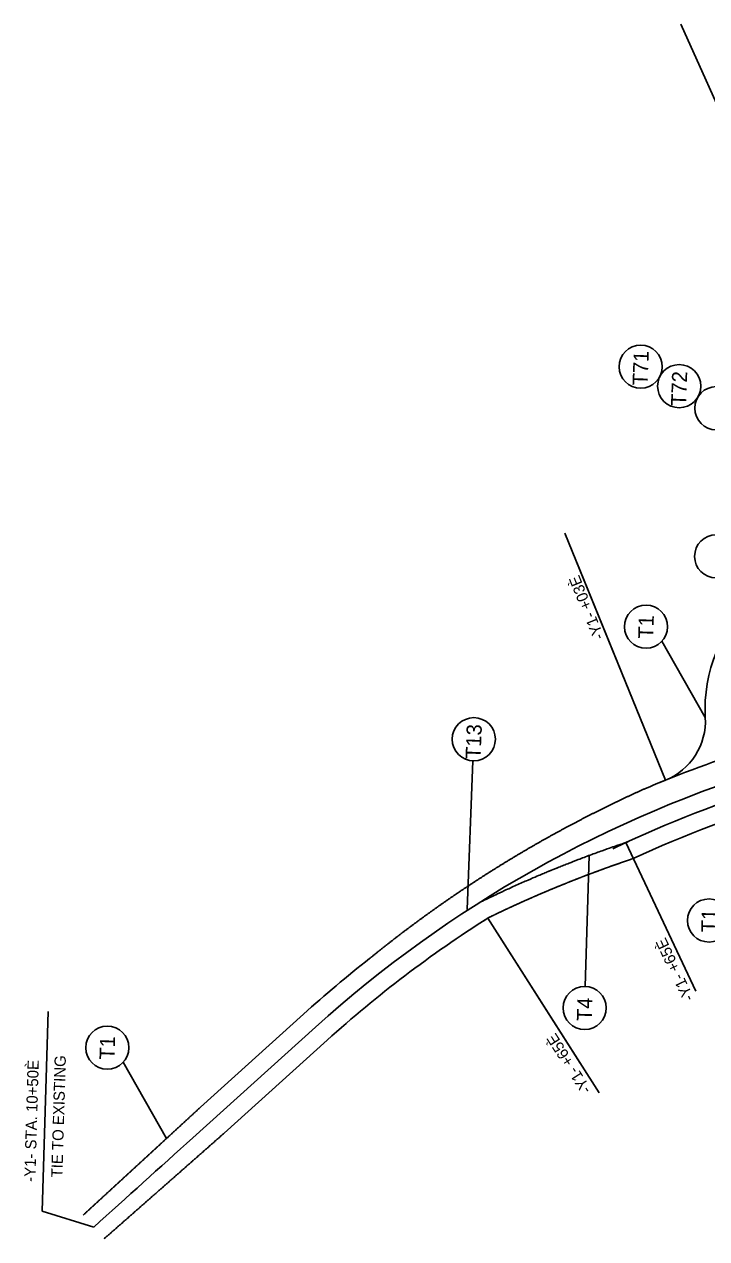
# Model space of a CAD drawing. Extents: x 1657109 to 2100937, y 684916 to 883211.
# Drawn here: x 2097100 to 2097527, y 685545 to 686305 of the extents above; entities that cross this region are included whole.
import ezdxf

# ---------------------------------------------------------------- set-up
doc = ezdxf.new("R2010")
doc.units = 0
for name, color, linetype in [('Prop CMT Pvmt Gravel', 7, 'Continuous'), ('Prop Conc 1ft 6in Curb and Gutter', 7, 'Continuous'), ('Prop Conc 2ft 6in Curb and Gutter', 7, 'Continuous'), ('Prop Dimension', 7, 'Continuous'), ('Prop Guardrail Anchor Unit CELL', 7, 'Continuous'), ('Prop Lane Arrow CELL', 7, 'Continuous'), ('Prop Sign E Chevron Right', 7, 'Continuous'), ('Scratch_Level_1', 7, 'Continuous')]:
    doc.layers.add(name, color=color, linetype=linetype)

msp = doc.modelspace()

# ---------------------------------------------------------------- linework, layer by layer
at = {"layer": 'Prop CMT Pvmt Gravel'}
for p, q in [((2097501.27, 685832.17), (2097438.41, 685986.71)), ((2097526.23, 685871.46), (2097499.11, 685919.12)), ((2097377.27, 685751.33), (2097380.84, 685844.33)), ((2097476.52, 685793.11), (2097520.28, 685700.17)), ((2097453.53, 685785.07), (2097451.14, 685703.18)), ((2097390.08, 685745.9), (2097459.86, 685636.58)), ((2097114.97, 685687.51), (2097111.34, 685562.51)), ((2097189.15, 685608.07), (2097162.04, 685655.73)), ((2097143.56, 685552.56), (2097111.34, 685562.51))]:
    msp.add_line(p, q, dxfattribs=at)
for centre in [(2097485.79, 686090.88), (2097509.88, 686078.71), (2097533.07, 686064.92), (2097533.02, 685972.21), (2097489.13, 685928.21), (2097381.36, 685857.82), (2097528.55, 685744.4), (2097450.75, 685689.68), (2097152.05, 685664.82)]:
    msp.add_circle(centre, 13.5, dxfattribs=at)
at = {"layer": 'Prop Conc 1ft 6in Curb and Gutter'}
msp.add_arc((2097791.55, 685113.58), 749, 106.65716, 114.87261, dxfattribs=at)
at = {"layer": 'Prop Conc 2ft 6in Curb and Gutter'}
msp.add_lwpolyline([(2097430.99, 685776.28), (2097431, 685776.28), (2097431, 685776.29)], dxfattribs=at)
for points in [[(2097431, 685776.29), (2097431.12, 685776.33), (2097431.3, 685776.41), (2097431.48, 685776.48), (2097431.6, 685776.53), (2097431.67, 685776.56), (2097431.84, 685776.63), (2097431.96, 685776.68), (2097432.11, 685776.74), (2097432.16, 685776.76), (2097432.2, 685776.77), (2097432.23, 685776.79), (2097432.25, 685776.79), (2097432.32, 685776.82), (2097432.86, 685777.04), (2097434.36, 685777.65), (2097437.73, 685779), (2097440.63, 685780.14), (2097446.42, 685782.4), (2097454.18, 685785.35), (2097461.98, 685788.16), (2097467.85, 685790.23), (2097470.79, 685791.25), (2097473.86, 685792.29), (2097474.97, 685792.66), (2097475.15, 685792.72), (2097475.21, 685792.74), (2097475.33, 685792.78), (2097475.46, 685792.83), (2097475.61, 685792.88), (2097475.7, 685792.91), (2097475.76, 685792.93), (2097475.79, 685792.94), (2097475.94, 685792.99), (2097476.07, 685793.03), (2097476.26, 685793.1), (2097476.32, 685793.12), (2097476.39, 685793.14), (2097476.4, 685793.14), (2097476.4, 685793.14), (2097476.41, 685793.14), (2097476.41, 685793.15), (2097476.41, 685793.15), (2097476.42, 685793.15), (2097476.44, 685793.16), (2097476.49, 685793.17), (2097476.66, 685793.23), (2097477.05, 685793.36), (2097477.42, 685793.48), (2097477.66, 685793.56)], [(2097385.26, 685755.79), (2097385.38, 685755.85), (2097385.55, 685755.93), (2097385.73, 685756.02), (2097385.85, 685756.07), (2097385.91, 685756.1), (2097386.08, 685756.19), (2097386.2, 685756.25), (2097386.34, 685756.32), (2097386.39, 685756.34), (2097386.43, 685756.36), (2097386.46, 685756.37), (2097386.47, 685756.38), (2097386.55, 685756.42), (2097387.08, 685756.67), (2097388.54, 685757.38), (2097391.84, 685758.97), (2097394.67, 685760.31), (2097400.35, 685762.97), (2097407.94, 685766.45), (2097415.6, 685769.8), (2097421.36, 685772.27), (2097424.24, 685773.49), (2097427.62, 685774.89), (2097429.13, 685775.52), (2097429.67, 685775.74), (2097429.74, 685775.77), (2097429.75, 685775.77), (2097429.76, 685775.78), (2097429.79, 685775.79), (2097429.84, 685775.81), (2097429.88, 685775.83), (2097430.04, 685775.89), (2097430.16, 685775.94), (2097430.34, 685776.01), (2097430.4, 685776.04), (2097430.52, 685776.09), (2097430.69, 685776.16), (2097430.87, 685776.23), (2097430.99, 685776.28)]]:
    msp.add_open_spline(points, degree=3, dxfattribs=at)
at = {"layer": 'Prop Dimension'}
for points in [[(2097497.79, 685830.75), (2097501.27, 685832.17), (2097445.89, 685968.3)], [(2097468.46, 685789.32), (2097476.52, 685793.11), (2097520.28, 685700.17)], [(2097387.18, 685744.05), (2097390.09, 685745.9), (2097447.99, 685655.16)]]:
    msp.add_lwpolyline(points, dxfattribs=at)
at = {"layer": 'Prop Guardrail Anchor Unit CELL'}
for p, q in [((2097210.46, 685627.69), (2097274.89, 685685.86)), ((2097225.2, 685611.36), (2097289.63, 685669.53))]:
    msp.add_line(p, q, dxfattribs=at)
for centre, radius, start, end in [((2097621.08, 685876.69), 95, 132.43424, 183.15611), ((2097486.29, 685869.26), 40, 291.99663, 3.15611), ((2097791.55, 685113.58), 775, 111.99663, 112.98788), ((2097791.55, 685113.58), 738, 106.65716, 114.87261), ((2097791.55, 685113.58), 749, 122.41153, 132.07604), ((2097791.55, 685113.58), 771, 128.06571, 132.07604)]:
    msp.add_arc(centre, radius, start, end, dxfattribs=at)
for points in [[(2097428.17, 685796.6), (2097428.97, 685797.05), (2097429.77, 685797.49), (2097430.57, 685797.94), (2097431.38, 685798.38), (2097432.18, 685798.82), (2097432.99, 685799.27), (2097433.79, 685799.71), (2097434.6, 685800.15), (2097435.4, 685800.58), (2097436.21, 685801.02), (2097437.01, 685801.46), (2097437.82, 685801.89), (2097438.63, 685802.33), (2097439.44, 685802.76), (2097440.25, 685803.2), (2097441.06, 685803.63), (2097441.87, 685804.06), (2097442.68, 685804.49), (2097443.49, 685804.92), (2097444.3, 685805.35), (2097445.11, 685805.77), (2097445.93, 685806.2), (2097446.74, 685806.63), (2097447.55, 685807.05), (2097448.37, 685807.47), (2097449.18, 685807.9), (2097450, 685808.32), (2097450.81, 685808.74), (2097451.63, 685809.16), (2097452.45, 685809.58), (2097453.26, 685809.99), (2097454.08, 685810.41), (2097454.9, 685810.83), (2097455.72, 685811.24), (2097456.54, 685811.65), (2097457.36, 685812.07), (2097458.18, 685812.48), (2097459, 685812.89), (2097459.82, 685813.3), (2097460.64, 685813.71), (2097461.47, 685814.12), (2097462.29, 685814.52), (2097463.11, 685814.93), (2097463.94, 685815.34), (2097464.76, 685815.74), (2097465.59, 685816.14), (2097466.41, 685816.55), (2097467.24, 685816.95), (2097468.06, 685817.35), (2097468.89, 685817.75), (2097469.72, 685818.15), (2097470.55, 685818.54), (2097471.37, 685818.94), (2097472.2, 685819.33), (2097473.03, 685819.73), (2097473.86, 685820.12), (2097474.69, 685820.51), (2097475.52, 685820.91), (2097476.36, 685821.3), (2097477.19, 685821.69), (2097478.02, 685822.08), (2097478.85, 685822.46), (2097479.69, 685822.85), (2097480.52, 685823.24), (2097481.35, 685823.62), (2097482.19, 685824), (2097483.02, 685824.39), (2097483.86, 685824.77), (2097484.69, 685825.15), (2097485.53, 685825.53), (2097486.37, 685825.91), (2097487.21, 685826.29), (2097488.88, 685827.04)], [(2097370.46, 685761.02), (2097371.21, 685761.54), (2097371.97, 685762.05), (2097372.73, 685762.56), (2097373.49, 685763.07), (2097374.25, 685763.58), (2097375.01, 685764.09), (2097375.77, 685764.6), (2097376.54, 685765.11), (2097377.3, 685765.62), (2097378.06, 685766.12), (2097378.83, 685766.63), (2097379.59, 685767.13), (2097380.36, 685767.63), (2097381.12, 685768.14), (2097381.89, 685768.64), (2097382.66, 685769.14), (2097383.43, 685769.64), (2097384.19, 685770.14), (2097384.96, 685770.63), (2097385.73, 685771.13), (2097386.5, 685771.63), (2097387.27, 685772.12), (2097388.05, 685772.62), (2097388.82, 685773.11), (2097389.59, 685773.6), (2097390.36, 685774.09), (2097391.14, 685774.58), (2097391.91, 685775.07), (2097392.69, 685775.56), (2097393.46, 685776.05), (2097394.24, 685776.54), (2097395.02, 685777.02), (2097395.79, 685777.51), (2097396.57, 685777.99), (2097397.35, 685778.47), (2097398.13, 685778.96), (2097398.91, 685779.44), (2097399.69, 685779.92), (2097400.47, 685780.4), (2097401.25, 685780.88), (2097402.03, 685781.36), (2097402.82, 685781.83), (2097403.6, 685782.31), (2097404.39, 685782.78), (2097405.17, 685783.26), (2097405.95, 685783.73), (2097406.74, 685784.2), (2097407.53, 685784.67), (2097408.31, 685785.14), (2097409.1, 685785.61), (2097409.89, 685786.08), (2097410.68, 685786.55), (2097411.47, 685787.02), (2097412.26, 685787.48), (2097413.05, 685787.95), (2097413.84, 685788.41), (2097414.63, 685788.87), (2097415.42, 685789.34), (2097416.21, 685789.8), (2097417.01, 685790.26), (2097417.8, 685790.72), (2097418.59, 685791.17), (2097419.39, 685791.63), (2097420.18, 685792.09), (2097420.98, 685792.54), (2097421.78, 685793), (2097422.57, 685793.45), (2097423.37, 685793.91), (2097424.17, 685794.36), (2097424.97, 685794.81), (2097425.77, 685795.26), (2097426.57, 685795.71), (2097427.37, 685796.16), (2097428.17, 685796.6)], [(2097435.16, 685766.1), (2097435.78, 685766.35), (2097436.39, 685766.6), (2097437.01, 685766.85), (2097437.63, 685767.1), (2097438.24, 685767.35), (2097438.86, 685767.6), (2097439.48, 685767.85), (2097440.09, 685768.1), (2097440.71, 685768.34), (2097441.33, 685768.59), (2097441.94, 685768.83), (2097442.56, 685769.08), (2097443.18, 685769.32), (2097443.8, 685769.57), (2097444.42, 685769.81), (2097445.03, 685770.05), (2097445.65, 685770.3), (2097446.27, 685770.54), (2097446.89, 685770.78), (2097447.51, 685771.02), (2097448.13, 685771.26), (2097448.75, 685771.5), (2097449.37, 685771.74), (2097449.99, 685771.97), (2097450.61, 685772.21), (2097451.23, 685772.45), (2097451.85, 685772.68), (2097452.47, 685772.92), (2097453.09, 685773.15), (2097453.71, 685773.39), (2097454.33, 685773.62), (2097454.95, 685773.86), (2097455.57, 685774.09), (2097456.19, 685774.32), (2097456.81, 685774.55), (2097457.43, 685774.78), (2097458.05, 685775.01), (2097458.67, 685775.24), (2097459.3, 685775.47), (2097459.92, 685775.7), (2097460.54, 685775.93), (2097461.16, 685776.16), (2097461.78, 685776.38), (2097462.41, 685776.61), (2097463.03, 685776.84), (2097463.65, 685777.06), (2097464.28, 685777.29), (2097464.9, 685777.51), (2097465.52, 685777.73), (2097466.14, 685777.96), (2097466.77, 685778.18), (2097467.39, 685778.4), (2097468.02, 685778.62), (2097468.64, 685778.84), (2097469.26, 685779.06), (2097469.89, 685779.28), (2097470.51, 685779.5), (2097471.14, 685779.72), (2097471.76, 685779.94), (2097472.39, 685780.15), (2097473.01, 685780.37), (2097473.63, 685780.59), (2097474.26, 685780.8), (2097474.89, 685781.02), (2097475.51, 685781.23), (2097476.14, 685781.44), (2097476.76, 685781.66), (2097477.39, 685781.87), (2097478.01, 685782.08), (2097478.64, 685782.29), (2097479.26, 685782.5), (2097479.89, 685782.71), (2097481.14, 685783.13)], [(2097390.09, 685745.9), (2097390.69, 685746.2), (2097391.29, 685746.49), (2097391.89, 685746.78), (2097392.5, 685747.08), (2097393.1, 685747.37), (2097393.7, 685747.66), (2097394.31, 685747.95), (2097394.91, 685748.24), (2097395.51, 685748.53), (2097396.12, 685748.82), (2097396.72, 685749.1), (2097397.33, 685749.39), (2097397.93, 685749.68), (2097398.53, 685749.97), (2097399.14, 685750.25), (2097399.74, 685750.54), (2097400.35, 685750.82), (2097400.96, 685751.11), (2097401.56, 685751.39), (2097402.17, 685751.67), (2097402.77, 685751.96), (2097403.38, 685752.24), (2097403.99, 685752.52), (2097404.59, 685752.8), (2097405.2, 685753.08), (2097405.81, 685753.36), (2097406.41, 685753.64), (2097407.02, 685753.92), (2097407.63, 685754.19), (2097408.24, 685754.47), (2097408.84, 685754.75), (2097409.45, 685755.02), (2097410.06, 685755.3), (2097410.67, 685755.57), (2097411.28, 685755.85), (2097411.89, 685756.12), (2097412.5, 685756.4), (2097413.11, 685756.67), (2097413.72, 685756.94), (2097414.33, 685757.21), (2097414.94, 685757.48), (2097415.55, 685757.75), (2097416.16, 685758.02), (2097416.77, 685758.29), (2097417.38, 685758.56), (2097417.99, 685758.83), (2097418.6, 685759.1), (2097419.21, 685759.36), (2097419.82, 685759.63), (2097420.43, 685759.9), (2097421.04, 685760.16), (2097421.66, 685760.43), (2097422.27, 685760.69), (2097422.88, 685760.95), (2097423.49, 685761.22), (2097424.11, 685761.48), (2097424.72, 685761.74), (2097425.33, 685762), (2097425.94, 685762.26), (2097426.56, 685762.52), (2097427.17, 685762.78), (2097427.78, 685763.04), (2097428.4, 685763.3), (2097429.01, 685763.56), (2097429.63, 685763.81), (2097430.24, 685764.07), (2097430.86, 685764.33), (2097431.47, 685764.58), (2097432.08, 685764.84), (2097432.7, 685765.09), (2097433.32, 685765.34), (2097433.93, 685765.6), (2097434.55, 685765.85), (2097435.16, 685766.1)], [(2097316.18, 685720.59), (2097316.89, 685721.17), (2097317.59, 685721.75), (2097318.31, 685722.32), (2097319.02, 685722.9), (2097319.73, 685723.47), (2097320.44, 685724.05), (2097321.15, 685724.62), (2097321.87, 685725.19), (2097322.58, 685725.76), (2097323.3, 685726.33), (2097324.01, 685726.9), (2097324.73, 685727.47), (2097325.45, 685728.03), (2097326.16, 685728.6), (2097326.88, 685729.17), (2097327.6, 685729.73), (2097328.32, 685730.29), (2097329.04, 685730.86), (2097329.76, 685731.42), (2097330.48, 685731.98), (2097331.21, 685732.54), (2097331.93, 685733.1), (2097332.65, 685733.66), (2097333.38, 685734.22), (2097334.1, 685734.78), (2097334.83, 685735.33), (2097335.56, 685735.89), (2097336.28, 685736.44), (2097337.01, 685737), (2097337.74, 685737.55), (2097338.47, 685738.1), (2097339.2, 685738.65), (2097339.93, 685739.2), (2097340.66, 685739.75), (2097341.39, 685740.3), (2097342.13, 685740.85), (2097342.86, 685741.4), (2097343.6, 685741.94), (2097344.33, 685742.49), (2097345.07, 685743.03), (2097345.8, 685743.58), (2097346.54, 685744.12), (2097347.28, 685744.66), (2097348.01, 685745.2), (2097348.75, 685745.74), (2097349.49, 685746.28), (2097350.23, 685746.82), (2097350.97, 685747.36), (2097351.71, 685747.89), (2097352.46, 685748.43), (2097353.2, 685748.96), (2097353.94, 685749.5), (2097354.69, 685750.03), (2097355.43, 685750.56), (2097356.17, 685751.09), (2097356.92, 685751.62), (2097357.67, 685752.15), (2097358.41, 685752.68), (2097359.16, 685753.21), (2097359.91, 685753.74), (2097360.66, 685754.26), (2097361.41, 685754.79), (2097362.16, 685755.31), (2097362.91, 685755.84), (2097363.66, 685756.36), (2097364.41, 685756.88), (2097365.17, 685757.4), (2097365.92, 685757.92), (2097366.68, 685758.44), (2097367.43, 685758.96), (2097368.19, 685759.48), (2097368.94, 685759.99), (2097369.7, 685760.51), (2097370.46, 685761.02)], [(2097210.46, 685627.69), (2097209.96, 685627.23), (2097209.46, 685626.78), (2097208.97, 685626.32), (2097208.47, 685625.86), (2097207.97, 685625.4), (2097207.48, 685624.95), (2097206.98, 685624.49), (2097206.48, 685624.03), (2097205.98, 685623.57), (2097205.49, 685623.11), (2097204.99, 685622.66), (2097204.49, 685622.2), (2097204, 685621.74), (2097203.5, 685621.28), (2097203, 685620.83), (2097202.51, 685620.37), (2097202.01, 685619.91), (2097201.51, 685619.45), (2097201.01, 685618.99), (2097200.52, 685618.54), (2097200.02, 685618.08), (2097199.52, 685617.62), (2097199.03, 685617.16), (2097198.53, 685616.71), (2097198.03, 685616.25), (2097197.54, 685615.79), (2097197.04, 685615.33), (2097196.54, 685614.87), (2097196.04, 685614.42), (2097195.55, 685613.96), (2097195.05, 685613.5), (2097194.55, 685613.04), (2097194.06, 685612.59), (2097193.56, 685612.13), (2097193.06, 685611.67), (2097192.57, 685611.21), (2097192.07, 685610.76), (2097191.57, 685610.3), (2097191.08, 685609.84), (2097190.58, 685609.38), (2097190.08, 685608.92), (2097189.58, 685608.47), (2097189.09, 685608.01), (2097188.59, 685607.55), (2097188.09, 685607.09), (2097187.6, 685606.64), (2097187.1, 685606.18), (2097186.6, 685605.72), (2097186.11, 685605.26), (2097185.61, 685604.81), (2097185.11, 685604.35), (2097184.61, 685603.89), (2097184.12, 685603.43), (2097183.62, 685602.98), (2097183.12, 685602.52), (2097182.63, 685602.06), (2097182.13, 685601.6), (2097181.63, 685601.15), (2097181.14, 685600.69), (2097180.64, 685600.23), (2097180.14, 685599.77), (2097179.64, 685599.32), (2097179.15, 685598.86), (2097178.65, 685598.4), (2097178.15, 685597.94), (2097177.66, 685597.49), (2097177.16, 685597.03), (2097176.66, 685596.57), (2097176.16, 685596.11), (2097175.67, 685595.66), (2097175.17, 685595.2), (2097174.67, 685594.74), (2097174.18, 685594.28), (2097173.68, 685593.83)], [(2097187.67, 685578.31), (2097188.17, 685578.76), (2097188.68, 685579.21), (2097189.19, 685579.65), (2097189.7, 685580.1), (2097190.2, 685580.55), (2097190.71, 685580.99), (2097191.22, 685581.44), (2097191.73, 685581.88), (2097192.23, 685582.33), (2097192.74, 685582.78), (2097193.25, 685583.22), (2097193.76, 685583.67), (2097194.26, 685584.12), (2097194.77, 685584.56), (2097195.28, 685585.01), (2097195.78, 685585.46), (2097196.29, 685585.9), (2097196.8, 685586.35), (2097197.31, 685586.8), (2097197.81, 685587.24), (2097198.32, 685587.69), (2097198.83, 685588.14), (2097199.34, 685588.58), (2097199.84, 685589.03), (2097200.35, 685589.48), (2097200.86, 685589.92), (2097201.37, 685590.37), (2097201.87, 685590.82), (2097202.38, 685591.26), (2097202.89, 685591.71), (2097203.39, 685592.16), (2097203.9, 685592.6), (2097204.41, 685593.05), (2097204.92, 685593.5), (2097205.42, 685593.94), (2097205.93, 685594.39), (2097206.44, 685594.84), (2097206.94, 685595.28), (2097207.45, 685595.73), (2097207.96, 685596.18), (2097208.47, 685596.62), (2097208.97, 685597.07), (2097209.48, 685597.52), (2097209.99, 685597.96), (2097210.49, 685598.41), (2097211, 685598.86), (2097211.51, 685599.3), (2097212.02, 685599.75), (2097212.52, 685600.2), (2097213.03, 685600.64), (2097213.54, 685601.09), (2097214.04, 685601.54), (2097214.55, 685601.98), (2097215.06, 685602.43), (2097215.57, 685602.88), (2097216.07, 685603.32), (2097216.58, 685603.77), (2097217.09, 685604.22), (2097217.59, 685604.66), (2097218.1, 685605.11), (2097218.61, 685605.56), (2097219.12, 685606), (2097219.62, 685606.45), (2097220.13, 685606.9), (2097220.64, 685607.34), (2097221.14, 685607.79), (2097221.65, 685608.24), (2097222.16, 685608.68), (2097222.66, 685609.13), (2097223.17, 685609.58), (2097223.68, 685610.02), (2097224.19, 685610.47), (2097225.2, 685611.36)], [(2097173.68, 685593.83), (2097173.18, 685593.37), (2097172.68, 685592.91), (2097172.19, 685592.45), (2097171.69, 685592), (2097171.19, 685591.54), (2097170.7, 685591.08), (2097170.2, 685590.62), (2097169.7, 685590.17), (2097169.2, 685589.71), (2097168.71, 685589.25), (2097168.21, 685588.79), (2097167.71, 685588.34), (2097167.21, 685587.88), (2097166.72, 685587.42), (2097166.22, 685586.97), (2097165.72, 685586.51), (2097165.23, 685586.05), (2097164.73, 685585.59), (2097164.23, 685585.14), (2097163.73, 685584.68), (2097163.24, 685584.22), (2097162.74, 685583.76), (2097162.24, 685583.31), (2097161.74, 685582.85), (2097161.25, 685582.39), (2097160.75, 685581.93), (2097160.25, 685581.48), (2097159.76, 685581.02), (2097159.26, 685580.56), (2097158.76, 685580.11), (2097158.26, 685579.65), (2097157.77, 685579.19), (2097157.27, 685578.73), (2097156.77, 685578.28), (2097156.27, 685577.82), (2097155.78, 685577.36), (2097155.28, 685576.91), (2097154.78, 685576.45), (2097154.28, 685575.99), (2097153.79, 685575.53), (2097153.29, 685575.08), (2097152.79, 685574.62), (2097152.3, 685574.16), (2097151.8, 685573.7), (2097151.3, 685573.25), (2097150.8, 685572.79), (2097150.31, 685572.33), (2097149.81, 685571.88), (2097149.31, 685571.42), (2097148.81, 685570.96), (2097148.32, 685570.5), (2097147.82, 685570.05), (2097147.32, 685569.59), (2097146.82, 685569.13), (2097146.33, 685568.68), (2097145.83, 685568.22), (2097145.33, 685567.76), (2097144.83, 685567.31), (2097144.34, 685566.85), (2097143.84, 685566.39), (2097143.34, 685565.93), (2097142.84, 685565.48), (2097142.35, 685565.02), (2097141.85, 685564.56), (2097141.35, 685564.11), (2097140.85, 685563.65), (2097140.36, 685563.19), (2097139.86, 685562.73), (2097139.36, 685562.28), (2097138.86, 685561.82), (2097138.37, 685561.36), (2097137.87, 685560.91), (2097136.87, 685559.99)], [(2097150.11, 685545.29), (2097150.61, 685545.74), (2097151.12, 685546.18), (2097151.63, 685546.63), (2097152.14, 685547.08), (2097152.64, 685547.52), (2097153.15, 685547.97), (2097153.66, 685548.41), (2097154.17, 685548.86), (2097154.67, 685549.31), (2097155.18, 685549.75), (2097155.69, 685550.2), (2097156.2, 685550.64), (2097156.71, 685551.09), (2097157.21, 685551.54), (2097157.72, 685551.98), (2097158.23, 685552.43), (2097158.74, 685552.88), (2097159.24, 685553.32), (2097159.75, 685553.77), (2097160.26, 685554.21), (2097160.77, 685554.66), (2097161.28, 685555.11), (2097161.78, 685555.55), (2097162.29, 685556), (2097162.8, 685556.44), (2097163.31, 685556.89), (2097163.81, 685557.34), (2097164.32, 685557.78), (2097164.83, 685558.23), (2097165.34, 685558.67), (2097165.84, 685559.12), (2097166.35, 685559.57), (2097166.86, 685560.01), (2097167.37, 685560.46), (2097167.87, 685560.91), (2097168.38, 685561.35), (2097168.89, 685561.8), (2097169.4, 685562.24), (2097169.9, 685562.69), (2097170.41, 685563.14), (2097170.92, 685563.58), (2097171.43, 685564.03), (2097171.94, 685564.48), (2097172.44, 685564.92), (2097172.95, 685565.37), (2097173.46, 685565.81), (2097173.97, 685566.26), (2097174.47, 685566.71), (2097174.98, 685567.15), (2097175.49, 685567.6), (2097176, 685568.05), (2097176.5, 685568.49), (2097177.01, 685568.94), (2097177.52, 685569.38), (2097178.03, 685569.83), (2097178.53, 685570.28), (2097179.04, 685570.72), (2097179.55, 685571.17), (2097180.06, 685571.62), (2097180.56, 685572.06), (2097181.07, 685572.51), (2097181.58, 685572.96), (2097182.09, 685573.4), (2097182.59, 685573.85), (2097183.1, 685574.29), (2097183.61, 685574.74), (2097184.12, 685575.19), (2097184.62, 685575.63), (2097185.13, 685576.08), (2097185.64, 685576.53), (2097186.15, 685576.97), (2097186.65, 685577.42), (2097187.16, 685577.87), (2097187.67, 685578.31)]]:
    msp.add_spline(points, degree=3, dxfattribs=at)
at = {"layer": 'Prop Lane Arrow CELL'}
msp.add_arc((2097791.55, 685113.58), 775, 106.65716, 111.99663, dxfattribs=at)
at = {"layer": 'Prop Sign E Chevron Right'}
msp.add_line((2097817.26, 685624.22), (2097510.8, 686305.14), dxfattribs=at)
at = {"layer": 'Scratch_Level_1'}
msp.add_line((2097205.52, 685608.42), (2097282.26, 685677.7), dxfattribs=at)
for centre, radius, start, end in [((2097791.55, 685113.58), 760, 106.65716, 132.07604), ((2059659.73, 727196.11), 56028.76, 311.990733, 312.076043)]:
    msp.add_arc(centre, radius, start, end, dxfattribs=at)

# ---------------------------------------------------------------- texts
at = {"layer": 'Prop CMT Pvmt Gravel'}
for s, height, rotation, p in [('T71', 9.45, 87.89056, (2097490.08, 686078.97)), ('T72', 9.45, 87.89056, (2097514.14, 686066.12)), ('-Y1- +03È', 7, 112.1354, (2097463.13, 685921.73)), ('T1', 9.45, 88.33483, (2097493.63, 685920.58)), ('T13', 9.45, 87.8037, (2097385.6, 685845.28)), ('T1', 9.45, 88.33483, (2097533.06, 685736.77)), ('-Y1- +65È', 7, 115.21323, (2097519.29, 685695.82)), ('T4', 9.45, 88.33483, (2097455.24, 685681.34)), ('T1', 9.45, 88.33483, (2097156.56, 685657.19)), ('-Y1- +65È', 7, 122.5471, (2097455.21, 685638.76)), ('-Y1- STA. 10+50È', 7, 88.33483, (2097107.01, 685580.8)), ('TIE TO EXISTING', 7, 88.33483, (2097123.94, 685583.53))]:
    msp.add_text(s, height=height, rotation=rotation, dxfattribs=at).set_placement(p)

doc.saveas('drawing.dxf')
